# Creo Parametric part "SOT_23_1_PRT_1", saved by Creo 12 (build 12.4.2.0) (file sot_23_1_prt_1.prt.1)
Units: Custom; MM, KILOGRAM, SECS

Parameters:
  PTC_WM_ITERATION = "0"
  PTC_WM_VERSION = "-.0"
  PTC_WM_LIFECYCLE_STATE = "In Work"
  PTC_WM_LIFECYCLE = "MO_CADDocument"
  PTC_WM_CREATED_BY = "Maximilian Roepper (Z0017RMS: MO)"
  PTC_WM_CREATED_ON = "18-Sep-26 11:36:42 AM"
  PTC_WM_MODIFIED_BY = "Maximilian Roepper (Z0017RMS: MO)"
  PTC_WM_MODIFIED_ON = "18-Sep-26 11:36:46 AM"
  PDMLINKNUMBER = "PDM000071454856"
  PTC_WM_NAME = "sot_23_1_prt_1.prt"
  PTC_WM_NUMBER = "PDM000071454856"

Other parameters: WEIGHT, WEIGHT_FACTOR, WEIGHT_ADD, _MASS_TEMP, _DIFF_TEMP, MC_ERRORS, SUPPLIER

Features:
  1. coordinate system
  2. datum plane "PRT_YZ"
  3. datum plane "PRT_XY"
  4. datum plane "PRT_XZ"
  5. coordinate system
  6. datum axis
  7. datum axis
  8. datum axis
  9. coordinate system
  10. imported feature
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
Other named items: PRT, SIEMENS_MO, DRW_VIEW_ORG, PRT_X, PRT_Y, PRT_Z, CS0, ROUGH_GROB

Layers: 00_STD_CSYS-KSYS, 01_STD_PLANES-EBENEN, 02_STD_AXES-ACHSEN, 03_STD_CSYS-KSYS, 24_IMPORT_FEAT-IMPORT_KE

Surfaces: 64 plane, 12 cylinder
